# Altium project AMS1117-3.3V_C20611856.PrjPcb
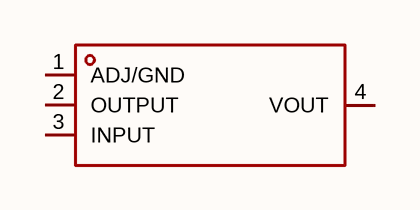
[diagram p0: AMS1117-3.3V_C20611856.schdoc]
1 sheet, 1 parts. Net scope: global (net labels, ports and power ports of the same name join across sheets).

## Sheet AMS1117-3.3V_C20611856.schdoc
size 127 x 101 mm

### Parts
U?  ams1117-3.3v_c20611856  [SOT-223-3_L6.5-W3.4-P2.30-LS7.0-BR]  (value not drawn)

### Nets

Not connected (* = marked no-connect by the designer): U? 1(ADJ/GND) 2(OUTPUT) 3(INPUT) 4(VOUT)

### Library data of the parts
U? = ams1117-3.3v_c20611856: 输出极性:正极;工作电压:12V;输出电压:3.3V;输出电流:1A;电源纹波抑制比(PSRR):-;输出类型:固定;; Manufacturer: TECH PUBLIC(台舟); AddInBom: yes; ModelId: 925194bf9823436183a3e0b978a8d076; ModelName: SOT-223-4P_L6.5-W3.5-H1.6-LS7.0-P2.30; ModelTransform: 279.89794,255.905,0,180,0,0,-3.9385,-0.0005,0; Output Configuration: 正极; Voltage - Supply: 12V; Output Voltage: 3.3V; Output Current: 1A; Voltage Dropout: 1.2V@(1A); standby current: 8mA; Output Type: 固定; Number of Outputs: 1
